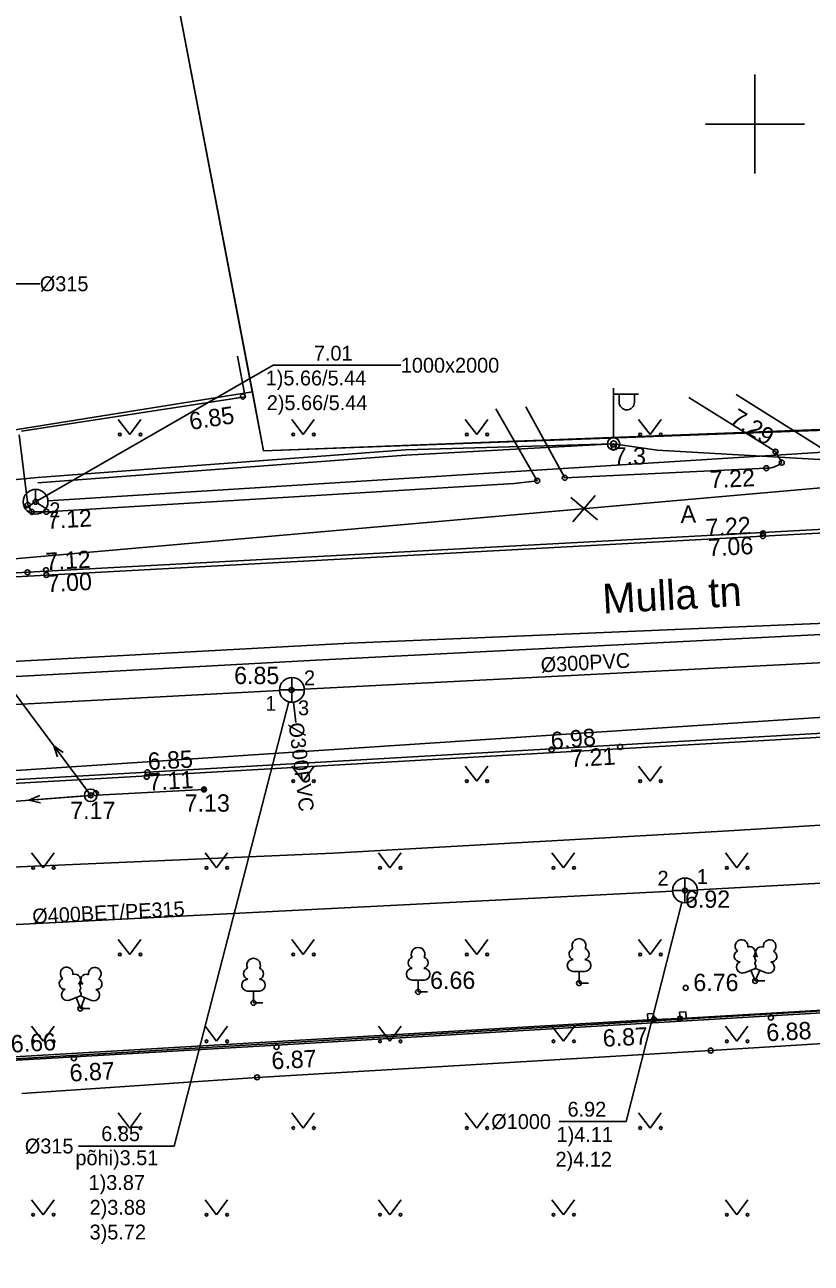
# Model space of a CAD drawing. Extents: x 473307 to 473719, y 6532843 to 6533381.
# Drawn here: x 473420.53 to 473452.27, y 6533254.01 to 6533304.01 of the extents above; entities that cross this region are included whole.
import ezdxf

# ---------------------------------------------------------------- set-up
doc = ezdxf.new("R2010")
doc.units = 0
for name, color, linetype in [('AED', 7, 'Continuous'), ('Default', 7, 'Continuous'), ('GTRASS', 7, 'Continuous'), ('HALJASTUS', 7, 'Continuous'), ('KKAEV', 7, 'Continuous'), ('KKAEV_NR', 7, 'Continuous'), ('KORGUS', 7, 'Continuous'), ('KPKAABEL', 7, 'Continuous'), ('KTRASS', 7, 'Continuous'), ('KTRASS_TEKST', 7, 'Continuous'), ('MPKAABEL', 7, 'Continuous'), ('MPOHULIIN', 7, 'Continuous'), ('PIIR', 7, 'Continuous'), ('POST', 7, 'Continuous'), ('PUU', 7, 'Continuous'), ('SIKAEV', 7, 'Continuous'), ('SIKAEV_NR', 7, 'Continuous'), ('SITRASS', 7, 'Continuous'), ('SKKAEV', 7, 'Continuous'), ('SKKAEV_NR', 7, 'Continuous'), ('SKTRASS', 7, 'Continuous'), ('SKTRASS_TEKST', 7, 'Continuous'), ('TEE', 7, 'Continuous'), ('TTRASS', 7, 'Continuous'), ('VORK', 7, 'Continuous'), ('VTRASS', 7, 'Continuous')]:
    doc.layers.add(name, color=color, linetype=linetype)

# ---------------------------------------------------------------- blocks, each defined once
blk = doc.blocks.new('VARPOS')
at = {"layer": 'Default'}
for p, q in [((-0.25, 0.25), (-0.25, -0.25)), ((-0.25, 0.25), (0.25, 0.25)), ((0.25, 0.25), (0.25, -0.25)), ((-0.25, -0.25), (0.25, -0.25))]:
    blk.add_line(p, q, dxfattribs=at)
blk = doc.blocks.new('LEHTP1')
at = {"layer": 'Default'}
for p, q in [((0.48, 0.95), (-0.48, 0.95)), ((0, 0), (0, 0.95)), ((0.76, 0), (0, 0))]:
    blk.add_line(p, q, dxfattribs=at)
for centre, radius, start, end in [((0, 3.04), 0.554, 332.5799, 207.4201), ((-0.34, 2.345), 0.465, 109.02174, 253.14154), ((0.34, 2.345), 0.465, 286.85082, 70.98591), ((-0.475, 1.425), 0.475, 90.0016, 269.3953), ((0.475, 1.425), 0.475, 270.6047, 89.9984)]:
    blk.add_arc(centre, radius, start, end, dxfattribs=at)
blk = doc.blocks.new('BEPOST')
at = {"layer": 'Default'}
for radius in [0.5, 0.0467]:
    blk.add_circle((0, 0), radius, dxfattribs=at)
blk = doc.blocks.new('MPSUUN')
at = {"layer": 'Default'}
for p, q in [((0.5, 0), (5, 0)), ((5, 0), (4.097, -0.297)), ((5, 0), (4.098, 0.3))]:
    blk.add_line(p, q, dxfattribs=at)
blk = doc.blocks.new('KAKAEV')
at = {"layer": 'Default'}
for p, q in [((0, -1), (0, 1)), ((-1, 0), (1, 0))]:
    blk.add_line(p, q, dxfattribs=at)
blk.add_circle((0, 0), 1, dxfattribs=at)
blk = doc.blocks.new('SIKAEV')
at = {"layer": 'Default'}
for p, q in [((0, 1), (0, 0)), ((0, 0), (-0.83, -0.55)), ((0, 0), (0.83, -0.55))]:
    blk.add_line(p, q, dxfattribs=at)
blk.add_circle((0, 0), 1, dxfattribs=at)
blk = doc.blocks.new('ANKURP')
at = {"layer": 'Default'}
for start, end in [(0, 180), (180, 0)]:
    blk.add_arc((0, 0), 0.125, start, end, dxfattribs=at)
blk = doc.blocks.new('LEHTP2')
at = {"layer": 'Default'}
for p, q in [((-0.88, 0.67), (0.01, 1.02)), ((0.01, 1.02), (0.89, 0.66)), ((0, 0), (-0.35, 0.88)), ((0, 0), (0.36, 0.88)), ((0.76, 0), (0, 0))]:
    blk.add_line(p, q, dxfattribs=at)
blk.add_lwpolyline([(0.01, 2.01), (-0.03, 1.86), (-0.03, 1.82), (-0.01, 1.76), (0.03, 1.69), (0.04, 1.65), (0.01, 1.58), (-0.04, 1.48), (-0.05, 1.43), (-0.04, 1.4), (-0.02, 1.34), (0.05, 1.22), (0.06, 1.18), (0.05, 1.14), (0.02, 1.07), (0.01, 1.02)], dxfattribs=at)
for centre, radius, start, end in [((-1.114, 2.828), 0.512, 111.50269, 232.51731), ((-1.114, 2.828), 0.512, 350.48556, 111.50017), ((1.158, 2.811), 0.512, 67.6168, 188.63142), ((1.158, 2.811), 0.512, 306.59966, 67.61428), ((-1.262, 2.005), 0.448, 111.43041, 274.49868), ((-0.445, 2.327), 0.448, 308.50412, 111.57247), ((0.008, 1.535), 0.475, 66.76552, 111.50149), ((0.481, 2.318), 0.45, 67.7016, 230.51262), ((1.293, 1.986), 0.448, 264.6183, 67.68657), ((-1.053, 1.117), 0.475, 111.50143, 291.50036), ((1.07, 1.101), 0.475, 247.61661, 67.61554)]:
    blk.add_arc(centre, radius, start, end, dxfattribs=at)
blk = doc.blocks.new('EITOOT')
at = {"layer": 'Default'}
for p, q in [((-0.99, 0.99), (0.99, -0.99)), ((-0.99, -0.99), (0.99, 0.99))]:
    blk.add_line(p, q, dxfattribs=at)
blk = doc.blocks.new('MEPOST')
at = {"layer": 'Default'}
blk.add_circle((0, 0), 0.5, dxfattribs=at)
for start, end in [(0, 180), (180, 0)]:
    blk.add_arc((0, 0), 0.25, start, end, dxfattribs=at)
blk = doc.blocks.new('VAPOST')
at = {"layer": 'Default'}
for p, q in [((0, 0.5), (0, 4.5)), ((0, 4), (2, 4)), ((0.453, 3.358), (0.453, 4)), ((1.679, 3.358), (1.679, 4))]:
    blk.add_line(p, q, dxfattribs=at)
blk.add_arc((1.066, 3.358), 0.613, 180, 0, dxfattribs=at)
blk = doc.blocks.new('MURU')
at = {"layer": 'Default'}
for p, q in [((-0.927, 1.213), (0, 0)), ((0, 0), (0.891, 1.213))]:
    blk.add_line(p, q, dxfattribs=at)
for centre in [(-0.802, 0), (0.856, 0)]:
    blk.add_circle(centre, 0.11, dxfattribs=at)
blk = doc.blocks.new('VKORIS')
at = {"layer": 'Default'}
for p, q in [((0, 4), (0, -4)), ((-4, 0), (4, 0))]:
    blk.add_line(p, q, dxfattribs=at)

msp = doc.modelspace()

# ---------------------------------------------------------------- linework, layer by layer
at = {"layer": 'AED'}
for points in [[(473429.115, 6533290.632), (473429.432, 6533288.984), (473420.406, 6533287.6)], [(473447.226, 6533263.902), (473496.402, 6533266.794), (473497.156, 6533266.092)], [(473384.104, 6533217.441), (473383.137, 6533220.726), (473372.835, 6533259.576), (473445.927, 6533263.844)], [(473445.927, 6533263.844), (473446.976, 6533263.888)]]:
    msp.add_lwpolyline(points, dxfattribs=at)
at = {"layer": 'GTRASS'}
msp.add_lwpolyline([(473352.971, 6533276.721), (473360.98, 6533278.32), (473373.58, 6533279.142), (473409.861, 6533281.542), (473476.35, 6533287.4), (473475.752, 6533290.633)], dxfattribs=at)
at = {"layer": 'KKAEV_NR'}
for points in [[(473411.434, 6533285.823), (473418.442, 6533293.551), (473421.14, 6533293.551)], [(473447.054, 6533268.573), (473444.8, 6533259.726), (473442.103, 6533259.726)]]:
    msp.add_lwpolyline(points, dxfattribs=at)
at = {"layer": 'KORGUS'}
for centre in [(473429.335, 6533288.998), (473444.299, 6533286.95), (473450.832, 6533286.773), (473451.084, 6533286.331), (473442.326, 6533285.717), (473450.46, 6533286.103), (473441.214, 6533285.599), (473420.97, 6533284.75), (473420.658, 6533284.622), (473420.815, 6533284.34), (473421.401, 6533284.347), (473450.321, 6533283.363), (473450.329, 6533283.477), (473420.641, 6533281.902), (473421.388, 6533281.988), (473421.403, 6533281.792), (473431.299, 6533277.149), (473441.792, 6533274.744), (473444.559, 6533274.852), (473425.485, 6533273.829), (473425.453, 6533273.648), (473423.194, 6533272.897), (473423.404, 6533272.983), (473427.768, 6533273.136), (473447.177, 6533269.057), (473442.902, 6533265.315), (473450.01, 6533265.402), (473436.407, 6533264.963), (473447.206, 6533265.125), (473422.775, 6533264.29), (473429.766, 6533264.522), (473445.927, 6533263.844), (473446.977, 6533263.882), (473450.644, 6533263.92), (473430.692, 6533262.74), (473422.516, 6533262.278), (473448.214, 6533262.592), (473429.907, 6533261.511)]:
    msp.add_circle(centre, 0.1, dxfattribs=at)
at = {"layer": 'KPKAABEL'}
msp.add_lwpolyline([(473353.442, 6533266.475), (473356.914, 6533266.999), (473362.351, 6533267.084), (473370.408, 6533267.159), (473390.326, 6533268.234), (473405.754, 6533269.007), (473418.445, 6533269.933), (473432.973, 6533270.56), (473448.952, 6533271.468), (473462.862, 6533272.322), (473472.995, 6533272.957), (473474.843, 6533272.925), (473475.447, 6533272.555), (473475.76, 6533272.032), (473476.188, 6533269.185), (473476.53, 6533268.446), (473476.993, 6533268.058), (473477.779, 6533268.045)], dxfattribs=at)
at = {"layer": 'KTRASS'}
for p, q in [((473447.677, 6533269.084), (473485.906, 6533271.173)), ((473400.337, 6533266.664), (473446.678, 6533269.032))]:
    msp.add_line(p, q, dxfattribs=at)
at = {"layer": 'MPKAABEL'}
for points in [[(473413.879, 6533285.041), (473421.046, 6533285.725), (473435.898, 6533286.846), (473444.295, 6533287.087), (473446.061, 6533286.839), (473454.024, 6533286.382), (473467.054, 6533286.286), (473479.314, 6533286.552), (473485.038, 6533287.191), (473485.942, 6533287.951), (473486.56, 6533287.104), (473507.071, 6533288.073), (473521.921, 6533288.182), (473522.937, 6533289.965), (473525.948, 6533290.824), (473539.287, 6533291.718)], [(473444.295, 6533287.087), (473446.061, 6533286.839), (473454.024, 6533286.382), (473467.054, 6533286.286), (473479.314, 6533286.552), (473485.038, 6533287.191), (473485.942, 6533287.951)], [(473401.884, 6533284.626), (473403.516, 6533284.394), (473413.879, 6533285.041), (473421.046, 6533285.725), (473435.898, 6533286.846), (473444.295, 6533287.087)], [(473421.064, 6533285.516), (473435.909, 6533286.636), (473444.295, 6533287.087)], [(473495.18, 6533225.875), (473494.734, 6533234.807), (473494.611, 6533236.968), (473494.449, 6533239.274), (473493.992, 6533245.232), (473493.386, 6533253.252), (473492.746, 6533261.702), (473492.562, 6533264.044), (473492.519, 6533264.695), (473492.434, 6533264.849), (473492.337, 6533264.926), (473492.01, 6533264.929), (473486.235, 6533264.685), (473483.652, 6533264.576), (473480.112, 6533264.424), (473477.661, 6533264.35), (473474.928, 6533264.258), (473473.125, 6533264.162), (473465.077, 6533263.639), (473448.214, 6533262.592), (473437.85, 6533261.982), (473429.907, 6533261.511), (473420.42, 6533260.861)]]:
    msp.add_lwpolyline(points, dxfattribs=at)
at = {"layer": 'MPOHULIIN'}
for points in [[(473413.769, 6533285.548), (473423.194, 6533272.897)], [(473423.194, 6533272.897), (473391.791, 6533270.484), (473361.09, 6533267.919), (473364.229, 6533220.925), (473380.477, 6533175.317), (473396.165, 6533131.758), (473413.567, 6533083.532), (473430.968, 6533052.6), (473459.84, 6533016.944), (473493.252, 6532975.715), (473524.159, 6532957.128), (473561.498, 6532934.712), (473599.705, 6532914.54), (473648.184, 6532910.183)]]:
    msp.add_lwpolyline(points, dxfattribs=at)
at = {"layer": 'PIIR'}
for points in [[(473449.76, 6533380.885), (473433.52, 6533372.29), (473447.71, 6533347.37), (473454.72, 6533346.94), (473461.17, 6533334.49), (473476.21, 6533307.58), (473471.79, 6533305.18), (473480.69, 6533288.74), (473430.17, 6533286.8), (473426.19, 6533307.67), (473415.91, 6533326.36), (473400.95, 6533323.6), (473392.61, 6533364.11), (473394.06, 6533370.53), (473399.03, 6533371.95), (473403.75, 6533374.68), (473415.377, 6533380.885)], [(473306.698, 6533269.314), (473318.22, 6533273.04), (473319.15, 6533273.32), (473325.84, 6533274.58), (473345.31, 6533277.99), (473387.78, 6533284.78), (473409.45, 6533285.94), (473429.73, 6533289.19), (473430.17, 6533286.8), (473480.73, 6533288.66), (473545.58, 6533292.4), (473585.1, 6533294.7), (473599.09, 6533295.91), (473601.54, 6533272.81), (473586.5, 6533271.93), (473496.37, 6533266.79), (473372.23, 6533259.41), (473356.5, 6533258.46), (473354.97, 6533266.17), (473326.61, 6533261.28), (473306.698, 6533254.866)]]:
    msp.add_lwpolyline(points, dxfattribs=at)
for points in [[(473400.95, 6533323.6), (473415.91, 6533326.36), (473426.19, 6533307.67), (473429.73, 6533289.19), (473409.45, 6533285.94)], [(473383.26, 6533220.83), (473372.23, 6533259.41), (473496.37, 6533266.79), (473499.84, 6533206.38), (473559.2, 6533209.37), (473561.43, 6533165.2), (473601.75, 6533167.04), (473607.56, 6533132.38), (473611.09, 6533109.85), (473618.6, 6533063.82), (473572.63, 6533056.43), (473548.5, 6533028.91), (473478.82, 6533017), (473455.33, 6533045.76), (473432.18, 6533083.36), (473429.59, 6533087.74), (473409.64, 6533129), (473385.1, 6533214.25), (473398.68, 6533216.8), (473398.11, 6533224.3)]]:
    msp.add_lwpolyline(points, close=True, dxfattribs=at)
at = {"layer": 'POST'}
msp.add_lwpolyline([(473423.444, 6533272.91), (473427.768, 6533273.136)], dxfattribs=at)
at = {"layer": 'SIKAEV_NR'}
msp.add_lwpolyline([(473420.97, 6533284.75), (473430.555, 6533290.263), (473435.71, 6533290.263)], dxfattribs=at)
at = {"layer": 'SITRASS'}
msp.add_line((473421.469, 6533284.782), (473480.248, 6533288.472), dxfattribs=at)
at = {"layer": 'SKKAEV_NR'}
msp.add_lwpolyline([(473431.19, 6533276.671), (473426.563, 6533258.738), (473422.708, 6533258.738)], dxfattribs=at)
at = {"layer": 'SKTRASS'}
for p, q in [((473390.084, 6533274.966), (473430.816, 6533277.129)), ((473431.376, 6533276.659), (473431.477, 6533275.836))]:
    msp.add_line(p, q, dxfattribs=at)
msp.add_lwpolyline([(473431.814, 6533277.181), (473489.624, 6533280.143)], dxfattribs=at)
at = {"layer": 'TEE'}
for points in [[(473447.33, 6533288.965), (473450.832, 6533286.773), (473451.084, 6533286.331)], [(473449.242, 6533289.077), (473453.333, 6533286.513)], [(473420.303, 6533287.457), (473420.658, 6533284.622), (473420.815, 6533284.34), (473421.401, 6533284.347), (473440.28, 6533285.485), (473441.214, 6533285.599), (473439.538, 6533288.507)], [(473450.46, 6533286.103), (473442.326, 6533285.717), (473440.758, 6533288.579)], [(473383.747, 6533279.941), (473388.989, 6533280.23), (473395.414, 6533280.514), (473421.395, 6533281.942), (473450.313, 6533283.513), (473463.939, 6533284.243), (473463.932, 6533284.415), (473464.724, 6533284.472), (473464.737, 6533284.29), (473472.444, 6533284.738)], [(473383.756, 6533279.791), (473388.996, 6533280.08), (473395.421, 6533280.364), (473421.403, 6533281.792), (473450.321, 6533283.363), (473464.095, 6533284.101), (473464.088, 6533284.276), (473464.585, 6533284.312), (473464.599, 6533284.132), (473472.462, 6533284.589)], [(473372.879, 6533270.945), (473396.372, 6533272.18), (473425.485, 6533273.829), (473455.75, 6533275.577), (473473.714, 6533276.578)], [(473372.901, 6533270.796), (473396.38, 6533272.03), (473425.493, 6533273.679), (473455.759, 6533275.427), (473473.724, 6533276.428)]]:
    msp.add_lwpolyline(points, dxfattribs=at)
msp.add_lwpolyline([(473396.254, 6533260.803), (473411.137, 6533261.686), (473430.688, 6533262.81), (473450.64, 6533263.99), (473471.14, 6533265.187), (473496.199, 6533266.651), (473497.903, 6533237.901), (473499.304, 6533214.158), (473499.292, 6533213.775), (473499.248, 6533213.313), (473499.158, 6533212.95), (473498.962, 6533212.533), (473498.665, 6533212.147), (473498.271, 6533211.83), (473497.797, 6533211.622), (473497.201, 6533211.492), (473496.826, 6533211.447), (473473.837, 6533210.118), (473452.83, 6533208.91), (473434.945, 6533207.846), (473416.821, 6533206.798), (473399.468, 6533205.756), (473398.532, 6533221.8), (473397.351, 6533241.472)], close=True, dxfattribs=at)
msp.add_arc((473450.454, 6533287.088), 0.985, 270.3633, 309.7797, dxfattribs=at)
at = {"layer": 'TTRASS'}
for points in [[(473353.109, 6533273.732), (473359.448, 6533274.47), (473364.817, 6533275.003), (473364.615, 6533277.039), (473366.54, 6533277.239), (473367.243, 6533277.321), (473369.251, 6533277.556), (473369.416, 6533275.425), (473378.385, 6533276.161), (473384.467, 6533276.364), (473409.656, 6533277.734), (473433.656, 6533279.045), (473458.306, 6533280.074), (473458.884, 6533280.111)], [(473353.128, 6533273.318), (473360.095, 6533274.113), (473365.18, 6533274.509), (473364.98, 6533276.522), (473366.064, 6533276.63), (473366.654, 6533276.702), (473368.689, 6533276.951), (473368.851, 6533274.868), (473378.363, 6533275.607), (473384.321, 6533275.885), (473408.317, 6533277.054), (473432.298, 6533278.353), (473456.899, 6533279.604), (473458.957, 6533279.712)]]:
    msp.add_lwpolyline(points, dxfattribs=at)
at = {"layer": 'VTRASS'}
msp.add_lwpolyline([(473353.303, 6533269.506), (473365.999, 6533272.186), (473379.745, 6533270.923), (473385.029, 6533271.056), (473412.227, 6533273.37), (473464.393, 6533276.821), (473499.973, 6533278.249), (473517.192, 6533279.473), (473556.042, 6533281.885), (473612.816, 6533284.928)], dxfattribs=at)

# ---------------------------------------------------------------- block references
at = {"layer": 'AED', "xscale": 0.5000000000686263, "yscale": 0.5, "rotation": 93.418869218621}
for p in [(473445.795, 6533263.961), (473447.094, 6533264.02)]:
    msp.add_blockref('VARPOS', p, dxfattribs=at)
at = {"layer": 'GTRASS', "xscale": 0.49999999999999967, "yscale": 0.4999999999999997, "rotation": 5.035160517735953}
msp.add_blockref('EITOOT', (473443.105, 6533284.471), dxfattribs=at)
at = {"layer": 'HALJASTUS', "xscale": 0.5, "yscale": 0.5}
for p in [(473424.771, 6533287.467), (473431.771, 6533287.467), (473438.771, 6533287.467), (473445.771, 6533287.467), (473431.771, 6533273.467), (473438.771, 6533273.467), (473445.771, 6533273.467), (473421.271, 6533269.967), (473428.271, 6533269.967), (473435.271, 6533269.967), (473442.271, 6533269.967), (473449.271, 6533269.967), (473424.771, 6533266.467), (473431.771, 6533266.467), (473438.771, 6533266.467), (473445.771, 6533266.467), (473421.271, 6533262.967), (473428.271, 6533262.967), (473435.271, 6533262.967), (473442.271, 6533262.967), (473449.271, 6533262.967), (473424.771, 6533259.467), (473431.771, 6533259.467), (473438.771, 6533259.467), (473445.771, 6533259.467), (473421.271, 6533255.967), (473428.271, 6533255.967), (473435.271, 6533255.967), (473442.271, 6533255.967), (473449.271, 6533255.967)]:
    msp.add_blockref('MURU', p, dxfattribs=at)
at = {"layer": 'KKAEV', "xscale": 0.5, "yscale": 0.5}
msp.add_blockref('KAKAEV', (473447.177, 6533269.057), dxfattribs=at)
at = {"layer": 'MPOHULIIN'}
for xscale, yscale, rotation in [(0.49999999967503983, 0.4999999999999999, 126.68612525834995), (0.49999999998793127, 0.5, -175.6060384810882)]:
    msp.add_blockref('MPSUUN', (473423.194, 6533272.897), dxfattribs=dict(at, xscale=xscale, yscale=yscale, rotation=rotation))
at = {"layer": 'POST', "xscale": 0.5, "yscale": 0.5}
for name, p in [('VAPOST', (473444.295, 6533287.087)), ('MEPOST', (473444.295, 6533287.087)), ('BEPOST', (473423.194, 6533272.897)), ('ANKURP', (473427.768, 6533273.136))]:
    msp.add_blockref(name, p, dxfattribs=at)
at = {"layer": 'PUU', "xscale": 0.5, "yscale": 0.5}
for name, p in [('LEHTP1', (473436.407, 6533264.963)), ('LEHTP1', (473442.902, 6533265.315)), ('LEHTP2', (473450.015, 6533265.402)), ('LEHTP1', (473429.766, 6533264.522)), ('LEHTP2', (473422.78, 6533264.29))]:
    msp.add_blockref(name, p, dxfattribs=at)
at = {"layer": 'SIKAEV', "xscale": 0.5, "yscale": 0.5}
msp.add_blockref('SIKAEV', (473420.97, 6533284.75), dxfattribs=at)
at = {"layer": 'SKKAEV', "xscale": 0.5, "yscale": 0.5}
msp.add_blockref('KAKAEV', (473431.315, 6533277.155), dxfattribs=at)
at = {"layer": 'VORK', "xscale": 0.5, "yscale": 0.5}
msp.add_blockref('VKORIS', (473450, 6533300), dxfattribs=at)

# ---------------------------------------------------------------- texts
at = {"layer": 'KKAEV_NR'}
for s, p in [('%%C315', (473421.14, 6533293.251)), ('2', (473446.067, 6533269.252)), ('1', (473447.655, 6533269.318)), ('6.92', (473442.437, 6533259.926)), ('%%c1000', (473439.36, 6533259.426)), ('1)4.11', (473441.995, 6533258.905)), ('2)4.12', (473441.952, 6533257.905))]:
    msp.add_text(s, height=0.6, dxfattribs=at).set_placement(p)
at = {"layer": 'KORGUS'}
for s, rotation, p in [('6.85', 8.8873, (473427.227, 6533287.644)), ('7.29', 327.9634, (473448.939, 6533287.958)), ('7.22', 2.7149, (473448.196, 6533285.295)), ('7.12', 3.4508, (473421.443, 6533283.648)), ('7.22', 3.1096, (473448.032, 6533283.352)), ('7.06', 3.1096, (473448.129, 6533282.543)), ('7.12', 3.1096, (473421.388, 6533281.988)), ('7.00', 3.1096, (473421.441, 6533281.093)), ('6.98', 5.2851, (473441.792, 6533274.744)), ('7.21', 3.3053, (473442.569, 6533274.036)), ('6.85', 3.3053, (473425.517, 6533273.918)), ('7.11', 3.3053, (473425.537, 6533273.087)), ('6.88', 3, (473450.476, 6533262.966)), ('6.66', 3.2891, (473419.988, 6533262.508)), ('6.87', 3.2891, (473443.878, 6533262.739)), ('6.87', 3, (473430.505, 6533261.834)), ('6.87', 3.0507, (473422.36, 6533261.339))]:
    msp.add_text(s, height=0.7, rotation=rotation, dxfattribs=at).set_placement(p)
for s, p in [('7.3', (473444.299, 6533286.25)), ('6.85', (473428.982, 6533277.389)), ('7.13', (473426.988, 6533272.239)), ('7.17', (473422.369, 6533271.94)), ('6.92', (473447.177, 6533268.357)), ('6.66', (473436.892, 6533265.084)), ('6.76', (473447.515, 6533264.995))]:
    msp.add_text(s, height=0.7, dxfattribs=at).set_placement(p)
at = {"layer": 'KTRASS_TEKST'}
msp.add_text('%%C400BET/PE315', height=0.6, rotation=2.9242, dxfattribs=at).set_placement((473420.851, 6533267.712))
at = {"layer": 'SIKAEV_NR'}
for s, p in [('7.01', (473432.199, 6533290.448)), ('1000x2000', (473435.71, 6533289.963)), ('1)5.66/5.44', (473430.256, 6533289.448)), ('2)5.66/5.44', (473430.299, 6533288.448)), ('2', (473421.525, 6533284.126))]:
    msp.add_text(s, height=0.6, dxfattribs=at).set_placement(p)
at = {"layer": 'SKKAEV_NR'}
for s, p in [('2', (473431.801, 6533277.341)), ('1', (473430.241, 6533276.31)), ('3', (473431.562, 6533276.131)), ('6.85', (473423.621, 6533258.938)), ('%%C315', (473420.536, 6533258.438)), ('põhi)3.51', (473422.578, 6533257.966)), ('1)3.87', (473423.107, 6533256.966)), ('2)3.88', (473423.15, 6533255.966)), ('3)5.72', (473423.15, 6533254.966))]:
    msp.add_text(s, height=0.6, dxfattribs=at).set_placement(p)
at = {"layer": 'SKTRASS_TEKST'}
for rotation, p in [(3.0744, (473441.371, 6533277.861)), (276.9919, (473431.179, 6533275.799))]:
    msp.add_text('%%C300PVC', height=0.6, rotation=rotation, dxfattribs=at).set_placement(p)
at = {"layer": 'TEE'}
for s, height, rotation, p in [('A', 0.7, 1.1118, (473447.006, 6533283.897)), ('Mulla tn', 1.2, 3.2461, (473443.878, 6533280.23))]:
    msp.add_text(s, height=height, rotation=rotation, dxfattribs=at).set_placement(p)

doc.saveas('drawing.dxf')
